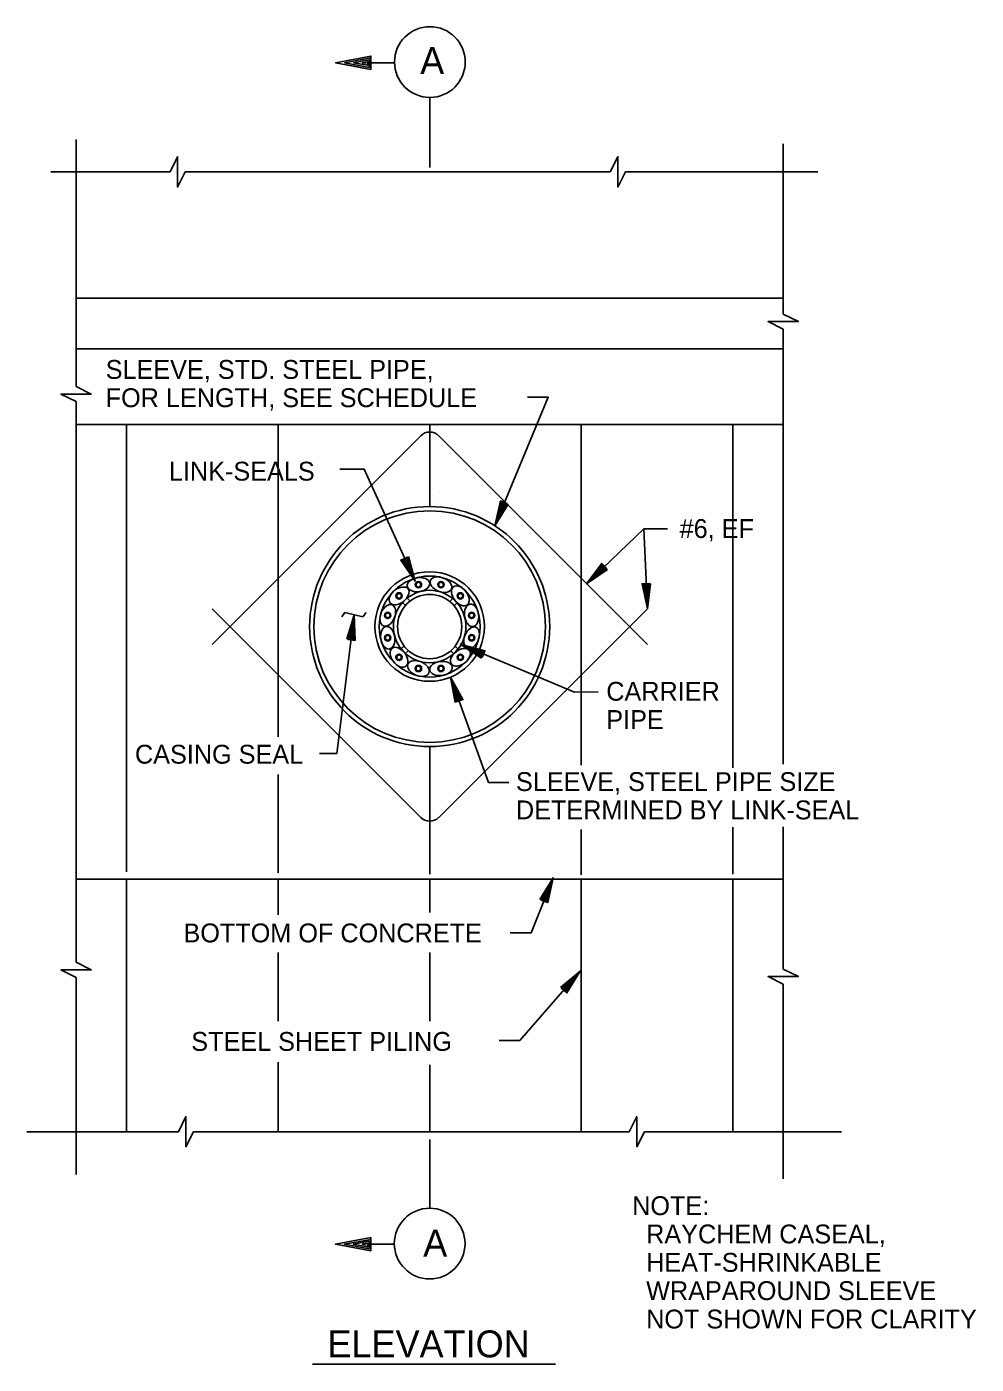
# Model space of a CAD drawing. Extents: x 22422.9 to 22498.9, y 22369.6 to 22415.
# Drawn here: x 22427.14 to 22436.54, y 22401.36 to 22414.6 of the extents above; entities that cross this region are included whole.
import ezdxf

# ---------------------------------------------------------------- set-up
doc = ezdxf.new("R2010")
doc.units = 0
for name, color, linetype in [('Level 1', 7, 'Continuous'), ('Level 10', 7, 'Continuous'), ('Level 2', 7, 'Continuous'), ('Level 3', 7, 'Continuous'), ('Level 4', 7, 'Continuous'), ('Level 8', 7, 'Continuous')]:
    doc.layers.add(name, color=color, linetype=linetype)

msp = doc.modelspace()

# ---------------------------------------------------------------- linework, layer by layer
at = {"layer": 'Level 1'}
for p, q in [((22427.63, 22411.037), (22427.63, 22413.482)), ((22434.63, 22411.755), (22434.63, 22413.441)), ((22427.379, 22413.161), (22428.56, 22413.161)), ((22428.71, 22413.161), (22432.918, 22413.161)), ((22433.068, 22413.161), (22434.973, 22413.161)), ((22434.63, 22407.299), (22434.63, 22411.605)), ((22427.63, 22405.338), (22427.63, 22410.888)), ((22427.63, 22410.661), (22434.63, 22410.661)), ((22428.13, 22406.232), (22428.13, 22410.661)), ((22429.63, 22407.569), (22429.63, 22410.661)), ((22431.13, 22409.849), (22431.13, 22410.661)), ((22432.63, 22407.288), (22432.63, 22410.661)), ((22434.13, 22407.264), (22434.13, 22410.661)), ((22431.217, 22409.929), (22431.217, 22409.929)), ((22431.223, 22409.998), (22431.223, 22409.998)), ((22430.85, 22409.227), (22430.85, 22409.227)), ((22430.865, 22409.159), (22430.865, 22409.159)), ((22430.89, 22408.869), (22430.861, 22408.899)), ((22430.936, 22408.912), (22430.906, 22408.942)), ((22431.328, 22408.91), (22431.358, 22408.939)), ((22431.373, 22408.866), (22431.403, 22408.896)), ((22430.289, 22408.801), (22430.26, 22408.757)), ((22430.289, 22408.801), (22430.467, 22408.757)), ((22430.373, 22408.758), (22430.373, 22408.758)), ((22430.467, 22408.757), (22430.502, 22408.801)), ((22430.367, 22408.689), (22430.367, 22408.689)), ((22431.536, 22408.594), (22431.536, 22408.594)), ((22433.062, 22408.707), (22433.062, 22408.707)), ((22433.062, 22408.707), (22433.062, 22408.707)), ((22433.062, 22408.615), (22433.062, 22408.615)), ((22433.062, 22408.615), (22433.062, 22408.615)), ((22433.091, 22408.677), (22433.091, 22408.677)), ((22433.091, 22408.677), (22433.091, 22408.677)), ((22433.091, 22408.645), (22433.091, 22408.645)), ((22433.091, 22408.645), (22433.091, 22408.645)), ((22430.847, 22408.441), (22430.876, 22408.47)), ((22431.411, 22408.437), (22431.381, 22408.466)), ((22431.603, 22408.576), (22431.603, 22408.576)), ((22430.889, 22408.395), (22430.919, 22408.424)), ((22431.368, 22408.391), (22431.338, 22408.421)), ((22430.989, 22408.213), (22430.989, 22408.213)), ((22430.97, 22408.146), (22430.97, 22408.146)), ((22432.17, 22408.119), (22432.17, 22408.119)), ((22432.17, 22408.119), (22432.17, 22408.119)), ((22432.238, 22408.132), (22432.238, 22408.132)), ((22432.238, 22408.132), (22432.238, 22408.132)), ((22431.13, 22406.21), (22431.13, 22407.474)), ((22429.63, 22406.222), (22429.63, 22407.197)), ((22432.63, 22406.205), (22432.63, 22406.652)), ((22434.13, 22406.21), (22434.13, 22406.674)), ((22434.63, 22405.271), (22434.63, 22406.68)), ((22427.63, 22403.238), (22427.63, 22405.188)), ((22432.575, 22405.197), (22432.575, 22405.197)), ((22432.62, 22405.25), (22432.62, 22405.25)), ((22434.63, 22403.195), (22434.63, 22405.122)), ((22427.142, 22403.661), (22428.643, 22403.661)), ((22428.793, 22403.661), (22433.105, 22403.661)), ((22433.255, 22403.661), (22435.207, 22403.661))]:
    msp.add_line(p, q, dxfattribs=at)
for points in [[(22428.56, 22413.161), (22428.635, 22413.311), (22428.635, 22413.011), (22428.71, 22413.161)], [(22432.918, 22413.161), (22432.993, 22413.311), (22432.993, 22413.011), (22433.068, 22413.161)], [(22434.63, 22411.605), (22434.48, 22411.68), (22434.78, 22411.68), (22434.63, 22411.755)], [(22427.63, 22410.888), (22427.48, 22410.962), (22427.78, 22410.962), (22427.63, 22411.037)], [(22427.63, 22405.188), (22427.48, 22405.263), (22427.78, 22405.263), (22427.63, 22405.338)], [(22434.63, 22405.122), (22434.48, 22405.196), (22434.78, 22405.196), (22434.63, 22405.271)], [(22428.643, 22403.661), (22428.718, 22403.811), (22428.718, 22403.511), (22428.793, 22403.661)], [(22433.105, 22403.661), (22433.18, 22403.811), (22433.18, 22403.511), (22433.255, 22403.661)]]:
    msp.add_lwpolyline(points, dxfattribs=at)
for centre, radius in [((22431.13, 22408.661), 1.188), ((22431.13, 22408.661), 1.146), ((22431.13, 22408.661), 0.542), ((22431.13, 22408.661), 0.5), ((22430.827, 22408.965), 0.0313), ((22431.019, 22409.076), 0.0313), ((22431.242, 22409.076), 0.0313), ((22431.434, 22408.965), 0.0313), ((22430.715, 22408.772), 0.0313), ((22431.545, 22408.772), 0.0313), ((22430.715, 22408.55), 0.0313), ((22431.545, 22408.55), 0.0313), ((22430.827, 22408.357), 0.0313), ((22431.434, 22408.357), 0.0313), ((22431.019, 22408.246), 0.0313), ((22431.242, 22408.246), 0.0313)]:
    msp.add_circle(centre, radius, dxfattribs=at)
for centre, major_axis in [((22431.019, 22409.076), (0.111, 0.015)), ((22431.242, 22409.076), (0.104, -0.043)), ((22430.827, 22408.965), (0.089, 0.0683)), ((22431.434, 22408.965), (0.0683, -0.089)), ((22430.715, 22408.772), (0.043, 0.104)), ((22431.545, 22408.772), (0.015, -0.111)), ((22430.715, 22408.55), (-0.015, 0.111)), ((22431.545, 22408.55), (-0.043, -0.104)), ((22430.827, 22408.357), (-0.0683, 0.089)), ((22431.434, 22408.357), (-0.089, -0.0683)), ((22431.019, 22408.246), (-0.104, 0.043)), ((22431.242, 22408.246), (-0.111, -0.015))]:
    msp.add_ellipse(centre, major_axis=major_axis, ratio=0.623518, dxfattribs=at)
at = {"layer": 'Level 10'}
for p, q in [((22431.042, 22410.55), (22428.976, 22408.484)), ((22433.285, 22408.484), (22431.219, 22410.55)), ((22431.042, 22406.772), (22428.976, 22408.838)), ((22433.285, 22408.838), (22431.219, 22406.772)), ((22432.376, 22401.359), (22429.969, 22401.359))]:
    msp.add_line(p, q, dxfattribs=at)
for centre, start, end in [((22431.13, 22410.462), 44.9997, 135), ((22431.13, 22406.86), 225, 315.0003)]:
    msp.add_arc(centre, 0.125, start, end, dxfattribs=at)
at = {"layer": 'Level 2'}
for p, q in [((22427.63, 22411.911), (22434.63, 22411.911)), ((22427.63, 22411.411), (22434.63, 22411.411)), ((22427.63, 22406.161), (22434.63, 22406.161)), ((22428.13, 22403.661), (22428.13, 22406.161)), ((22429.63, 22405.809), (22429.63, 22406.161)), ((22431.13, 22405.831), (22431.13, 22406.161)), ((22432.63, 22403.661), (22432.63, 22406.161)), ((22434.13, 22403.661), (22434.13, 22406.161)), ((22429.63, 22404.756), (22429.63, 22405.436)), ((22431.13, 22404.756), (22431.13, 22405.436)), ((22432.021, 22404.563), (22432.62, 22405.25)), ((22431.818, 22404.563), (22432.021, 22404.563)), ((22429.63, 22403.661), (22429.63, 22404.348)), ((22431.13, 22403.661), (22431.13, 22404.323))]:
    msp.add_line(p, q, dxfattribs=at)
for points in [[(22432.099, 22410.931), (22432.304, 22410.931), (22431.774, 22409.659)], [(22430.241, 22410.22), (22430.483, 22410.22), (22430.985, 22409.11)], [(22431.908, 22409.873), (22431.774, 22409.659), (22431.832, 22409.905), (22431.897, 22409.878), (22431.801, 22409.723), (22431.84, 22409.89), (22431.882, 22409.873), (22431.826, 22409.785), (22431.848, 22409.875), (22431.865, 22409.868), (22431.853, 22409.849)], [(22433.25, 22409.628), (22432.683, 22409.083)], [(22433.483, 22409.628), (22433.25, 22409.628), (22433.285, 22408.838)], [(22430.919, 22409.354), (22430.985, 22409.11), (22430.844, 22409.32), (22430.909, 22409.349), (22430.956, 22409.173), (22430.861, 22409.316), (22430.902, 22409.335), (22430.929, 22409.234), (22430.877, 22409.312), (22430.894, 22409.32), (22430.9, 22409.297)], [(22432.891, 22409.226), (22432.683, 22409.083), (22432.834, 22409.286), (22432.883, 22409.235), (22432.733, 22409.131), (22432.835, 22409.269), (22432.867, 22409.236), (22432.781, 22409.178), (22432.837, 22409.252), (22432.85, 22409.238), (22432.831, 22409.226)], [(22433.315, 22409.089), (22433.285, 22408.838), (22433.232, 22409.085), (22433.303, 22409.088), (22433.282, 22408.907), (22433.246, 22409.075), (22433.291, 22409.077), (22433.279, 22408.974), (22433.26, 22409.065), (22433.279, 22409.066), (22433.276, 22409.043)], [(22430.04, 22407.406), (22430.21, 22407.406), (22430.381, 22408.777)], [(22430.309, 22408.535), (22430.381, 22408.777), (22430.391, 22408.524), (22430.321, 22408.533), (22430.373, 22408.708), (22430.38, 22408.537), (22430.335, 22408.542), (22430.364, 22408.642), (22430.368, 22408.549), (22430.349, 22408.551), (22430.356, 22408.573)], [(22432.797, 22408.014), (22432.563, 22408.013), (22431.432, 22408.487)], [(22431.643, 22408.347), (22431.432, 22408.487), (22431.677, 22408.422), (22431.648, 22408.358), (22431.496, 22408.458), (22431.662, 22408.414), (22431.643, 22408.373), (22431.556, 22408.431), (22431.646, 22408.407), (22431.639, 22408.39), (22431.62, 22408.402)], [(22431.912, 22407.118), (22431.713, 22407.118), (22431.336, 22408.16)], [(22431.382, 22407.911), (22431.336, 22408.16), (22431.459, 22407.939), (22431.393, 22407.915), (22431.359, 22408.095), (22431.443, 22407.945), (22431.401, 22407.929), (22431.382, 22408.032), (22431.427, 22407.95), (22431.41, 22407.944), (22431.406, 22407.967)], [(22431.928, 22405.63), (22432.135, 22405.63), (22432.351, 22406.175)], [(22432.221, 22405.958), (22432.351, 22406.175), (22432.298, 22405.928), (22432.232, 22405.954), (22432.325, 22406.11), (22432.289, 22405.943), (22432.247, 22405.959), (22432.301, 22406.048), (22432.281, 22405.957), (22432.263, 22405.964), (22432.275, 22405.984)], [(22432.425, 22405.089), (22432.62, 22405.25), (22432.488, 22405.035), (22432.434, 22405.081), (22432.575, 22405.197), (22432.485, 22405.051), (22432.45, 22405.081), (22432.531, 22405.147), (22432.482, 22405.068), (22432.467, 22405.08), (22432.485, 22405.095)]]:
    msp.add_lwpolyline(points, dxfattribs=at)
for radius in [0.359, 0.318]:
    msp.add_circle((22431.13, 22408.661), radius, dxfattribs=at)
at = {"layer": 'Level 3'}
for p, q in [((22430.549, 22414.242), (22430.782, 22414.242)), ((22431.132, 22413.204), (22431.132, 22413.892)), ((22431.13, 22403.584), (22431.13, 22402.896)), ((22430.547, 22402.546), (22430.78, 22402.546))]:
    msp.add_line(p, q, dxfattribs=at)
for points in [[(22430.549, 22414.291), (22430.549, 22414.308), (22430.199, 22414.242), (22430.549, 22414.177), (22430.549, 22414.291), (22430.288, 22414.243), (22430.532, 22414.196), (22430.532, 22414.272), (22430.376, 22414.243), (22430.516, 22414.217), (22430.516, 22414.252), (22430.465, 22414.243), (22430.499, 22414.237)], [(22430.547, 22402.595), (22430.547, 22402.613), (22430.197, 22402.546), (22430.547, 22402.481), (22430.547, 22402.595), (22430.286, 22402.547), (22430.53, 22402.501), (22430.53, 22402.576), (22430.374, 22402.547), (22430.513, 22402.521), (22430.513, 22402.556), (22430.463, 22402.547), (22430.496, 22402.541)]]:
    msp.add_lwpolyline(points, dxfattribs=at)
for centre in [(22431.132, 22414.249), (22431.13, 22402.553)]:
    msp.add_circle(centre, 0.35, dxfattribs=at)
at = {"layer": 'Level 8'}
for p, q in [((22431.774, 22409.659), (22431.774, 22409.659)), ((22431.801, 22409.723), (22431.801, 22409.723)), ((22430.956, 22409.173), (22430.956, 22409.173)), ((22432.733, 22409.131), (22432.733, 22409.131)), ((22430.807, 22408.984), (22430.8, 22408.958)), ((22430.807, 22408.984), (22430.834, 22408.991)), ((22430.853, 22408.972), (22430.834, 22408.991)), ((22430.985, 22409.11), (22430.985, 22409.11)), ((22431.012, 22409.102), (22430.993, 22409.083)), ((22431, 22409.057), (22430.993, 22409.083)), ((22431.026, 22409.05), (22431, 22409.057)), ((22431.012, 22409.102), (22431.038, 22409.095)), ((22431.026, 22409.05), (22431.045, 22409.069)), ((22431.045, 22409.069), (22431.038, 22409.095)), ((22431.215, 22409.069), (22431.222, 22409.095)), ((22431.235, 22409.05), (22431.215, 22409.069)), ((22431.249, 22409.102), (22431.222, 22409.095)), ((22431.235, 22409.05), (22431.261, 22409.057)), ((22431.249, 22409.102), (22431.268, 22409.083)), ((22431.261, 22409.057), (22431.268, 22409.083)), ((22431.408, 22408.972), (22431.427, 22408.991)), ((22431.453, 22408.984), (22431.427, 22408.991)), ((22431.453, 22408.984), (22431.46, 22408.958)), ((22432.683, 22409.083), (22432.683, 22409.083)), ((22430.819, 22408.939), (22430.8, 22408.958)), ((22430.846, 22408.946), (22430.819, 22408.939)), ((22430.846, 22408.946), (22430.853, 22408.972)), ((22431.415, 22408.946), (22431.408, 22408.972)), ((22431.415, 22408.946), (22431.441, 22408.939)), ((22431.441, 22408.939), (22431.46, 22408.958)), ((22433.282, 22408.907), (22433.282, 22408.907)), ((22430.381, 22408.777), (22430.381, 22408.777)), ((22430.689, 22408.779), (22430.708, 22408.798)), ((22430.689, 22408.779), (22430.696, 22408.753)), ((22430.722, 22408.746), (22430.696, 22408.753)), ((22430.734, 22408.791), (22430.708, 22408.798)), ((22430.741, 22408.765), (22430.722, 22408.746)), ((22430.741, 22408.765), (22430.734, 22408.791)), ((22431.519, 22408.765), (22431.526, 22408.791)), ((22431.519, 22408.765), (22431.539, 22408.746)), ((22431.526, 22408.791), (22431.552, 22408.798)), ((22431.539, 22408.746), (22431.564, 22408.753)), ((22431.571, 22408.779), (22431.552, 22408.798)), ((22431.571, 22408.779), (22431.564, 22408.753)), ((22433.285, 22408.838), (22433.285, 22408.838)), ((22430.373, 22408.708), (22430.373, 22408.708)), ((22430.689, 22408.543), (22430.696, 22408.569)), ((22430.689, 22408.543), (22430.708, 22408.524)), ((22430.722, 22408.576), (22430.696, 22408.569)), ((22430.734, 22408.531), (22430.708, 22408.524)), ((22430.741, 22408.557), (22430.722, 22408.576)), ((22430.741, 22408.557), (22430.734, 22408.531)), ((22431.432, 22408.487), (22431.432, 22408.487)), ((22431.496, 22408.458), (22431.496, 22408.458)), ((22431.519, 22408.557), (22431.539, 22408.576)), ((22431.519, 22408.557), (22431.526, 22408.531)), ((22431.526, 22408.531), (22431.552, 22408.524)), ((22431.539, 22408.576), (22431.564, 22408.569)), ((22431.571, 22408.543), (22431.552, 22408.524)), ((22431.571, 22408.543), (22431.564, 22408.569)), ((22430.82, 22408.383), (22430.801, 22408.364)), ((22430.808, 22408.338), (22430.801, 22408.364)), ((22430.808, 22408.338), (22430.834, 22408.331)), ((22430.846, 22408.376), (22430.82, 22408.383)), ((22430.853, 22408.35), (22430.834, 22408.331)), ((22430.846, 22408.376), (22430.853, 22408.35)), ((22431.415, 22408.376), (22431.408, 22408.35)), ((22431.408, 22408.35), (22431.427, 22408.331)), ((22431.415, 22408.376), (22431.441, 22408.383)), ((22431.453, 22408.338), (22431.427, 22408.331)), ((22431.441, 22408.383), (22431.46, 22408.364)), ((22431.453, 22408.338), (22431.46, 22408.364)), ((22431, 22408.265), (22430.993, 22408.239)), ((22431.012, 22408.22), (22430.993, 22408.239)), ((22431.026, 22408.272), (22431, 22408.265)), ((22431.012, 22408.22), (22431.038, 22408.227)), ((22431.026, 22408.272), (22431.045, 22408.253)), ((22431.045, 22408.253), (22431.038, 22408.227)), ((22431.235, 22408.272), (22431.216, 22408.253)), ((22431.216, 22408.253), (22431.223, 22408.227)), ((22431.249, 22408.22), (22431.223, 22408.227)), ((22431.235, 22408.272), (22431.261, 22408.265)), ((22431.249, 22408.22), (22431.268, 22408.239)), ((22431.261, 22408.265), (22431.268, 22408.239)), ((22431.336, 22408.16), (22431.336, 22408.16)), ((22431.359, 22408.095), (22431.359, 22408.095)), ((22432.325, 22406.11), (22432.325, 22406.11)), ((22432.351, 22406.175), (22432.351, 22406.175))]:
    msp.add_line(p, q, dxfattribs=at)
for centre in [(22430.827, 22408.965), (22431.019, 22409.076), (22431.242, 22409.076), (22431.434, 22408.965), (22430.715, 22408.772), (22431.545, 22408.772), (22430.715, 22408.55), (22431.545, 22408.55), (22430.827, 22408.357), (22431.434, 22408.357), (22431.019, 22408.246), (22431.242, 22408.246)]:
    msp.add_circle(centre, 0.0233, dxfattribs=at)

# ---------------------------------------------------------------- texts
at = {"layer": 'Level 3'}
for s, height, p in [('A', 0.267, (22431.036, 22414.13)), ('A', 0.267, (22431.066, 22402.425)), ('ELEVATION', 0.2667, (22430.118, 22401.427))]:
    msp.add_text(s, height=height, dxfattribs=at).set_placement(p)
at = {"layer": 'Level 4'}
for s, height, p in [('SLEEVE, STD. STEEL PIPE,', 0.18667, (22427.923, 22411.113)), ('FOR LENGTH, SEE SCHEDULE', 0.18667, (22427.923, 22410.833)), ('LINK-SEALS', 0.1867, (22428.549, 22410.106)), ('#6, EF', 0.1867, (22433.604, 22409.538)), ('CARRIER', 0.1867, (22432.878, 22407.927)), ('PIPE', 0.1867, (22432.878, 22407.647)), ('CASING SEAL', 0.18667, (22428.213, 22407.304)), ('SLEEVE, STEEL PIPE SIZE', 0.18667, (22431.984, 22407.033)), ('DETERMINED BY LINK-SEAL', 0.18667, (22431.984, 22406.753)), ('BOTTOM OF CONCRETE', 0.18667, (22428.693, 22405.535)), ('STEEL SHEET PILING', 0.18667, (22428.77, 22404.461)), ('NOTE:', 0.1867, (22433.134, 22402.835)), ('  RAYCHEM CASEAL,', 0.18667, (22433.134, 22402.555)), ('  HEAT-SHRINKABLE', 0.18667, (22433.134, 22402.274)), ('  WRAPAROUND SLEEVE', 0.18667, (22433.134, 22401.994)), ('  NOT SHOWN FOR CLARITY', 0.18667, (22433.134, 22401.713))]:
    msp.add_text(s, height=height, dxfattribs=at).set_placement(p)

doc.saveas('drawing.dxf')
